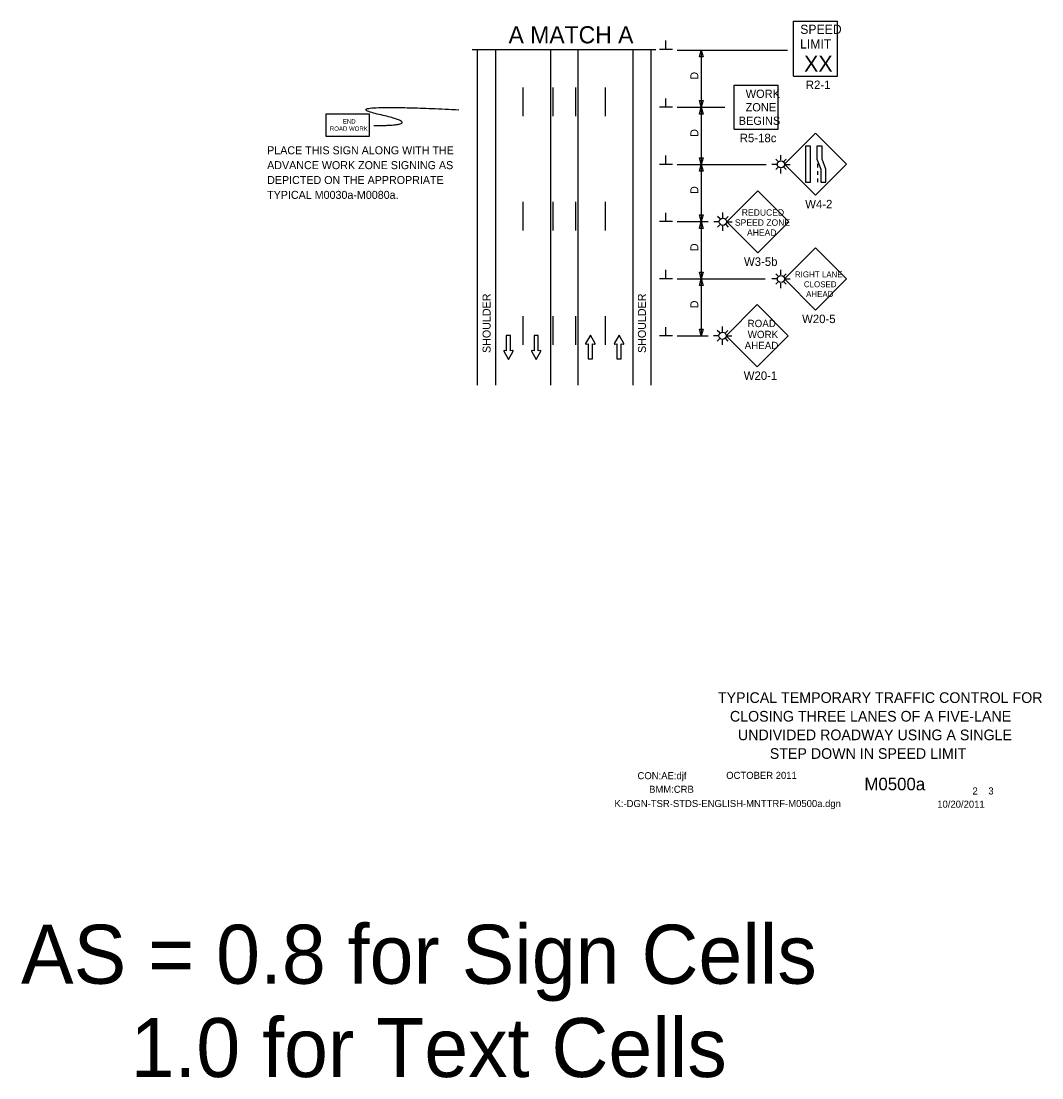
# Model space of a CAD drawing. Extents: x 16738 to 19504, y 5697 to 6916.
# Drawn here: x 17580 to 18473, y 5697 to 6621 of the extents above; entities that cross this region are included whole.
import ezdxf

# ---------------------------------------------------------------- set-up
doc = ezdxf.new("R2010")
doc.units = 0
for name, color, linetype in [('ALI_LEGAL_EX', 7, 'Continuous'), ('BORDER', 7, 'Continuous'), ('BORDER_SIGNAL_WO', 7, 'Continuous'), ('MT_SCRATCH_LEVEL_E', 7, 'Continuous'), ('PAVT_EDGE_EX', 7, 'Continuous'), ('TRAFFIC_SIGNS_PR', 7, 'Continuous'), ('TYPICAL_TEXT_DIMEN_PR', 7, 'Continuous')]:
    doc.layers.add(name, color=color, linetype=linetype)

msp = doc.modelspace()

# ---------------------------------------------------------------- linework, layer by layer
at = {"layer": 'ALI_LEGAL_EX'}
for points in [[(18019.48, 6563.08), (18019.48, 6538.08)], [(18045.48, 6563.08), (18045.48, 6538.08)], [(18065.48, 6563.08), (18065.48, 6538.08)], [(18091.48, 6563.08), (18091.48, 6538.08)], [(18019.48, 6463.08), (18019.48, 6438.08)], [(18045.48, 6463.08), (18045.48, 6438.08)], [(18065.48, 6463.08), (18065.48, 6438.08)], [(18091.48, 6463.08), (18091.48, 6438.08)], [(18019.48, 6363.08), (18019.48, 6338.08)], [(18045.48, 6363.08), (18045.48, 6338.08)], [(18065.48, 6363.08), (18065.48, 6338.08)], [(18091.48, 6363.08), (18091.48, 6338.08)]]:
    msp.add_lwpolyline(points, dxfattribs=at)
at = {"layer": 'MT_SCRATCH_LEVEL_E'}
for p, q in [((18008.68, 6346.05), (18004.93, 6346.05)), ((18004.93, 6346.05), (18004.93, 6332.79)), ((18008.68, 6346.05), (18004.93, 6346.05)), ((18004.93, 6346.05), (18004.93, 6332.79)), ((18008.68, 6332.79), (18008.68, 6346.05)), ((18008.68, 6332.79), (18008.68, 6346.05)), ((18032.93, 6346.05), (18029.19, 6346.05)), ((18029.19, 6346.05), (18029.19, 6332.79)), ((18032.93, 6346.05), (18029.19, 6346.05)), ((18029.19, 6346.05), (18029.19, 6332.79)), ((18032.93, 6332.79), (18032.93, 6346.05)), ((18032.93, 6332.79), (18032.93, 6346.05)), ((18078.44, 6346.51), (18074.33, 6339.27)), ((18078.44, 6346.51), (18074.33, 6339.27)), ((18082.59, 6339.27), (18078.44, 6346.51)), ((18082.59, 6339.27), (18078.44, 6346.51)), ((18103.53, 6346.51), (18099.42, 6339.27)), ((18103.53, 6346.51), (18099.42, 6339.27)), ((18107.68, 6339.27), (18103.53, 6346.51)), ((18107.68, 6339.27), (18103.53, 6346.51)), ((18002.68, 6332.42), (18006.82, 6325.18)), ((18002.68, 6332.42), (18006.82, 6325.18)), ((18004.93, 6332.79), (18003.16, 6333.11)), ((18004.93, 6332.79), (18003.16, 6333.11)), ((18006.82, 6325.18), (18010.94, 6332.42)), ((18006.82, 6325.18), (18010.94, 6332.42)), ((18010.45, 6333.11), (18008.68, 6332.79)), ((18010.45, 6333.11), (18008.68, 6332.79)), ((18026.93, 6332.42), (18031.08, 6325.18)), ((18026.93, 6332.42), (18031.08, 6325.18)), ((18029.19, 6332.79), (18027.41, 6333.11)), ((18029.19, 6332.79), (18027.41, 6333.11)), ((18031.08, 6325.18), (18035.19, 6332.42)), ((18031.08, 6325.18), (18035.19, 6332.42)), ((18034.71, 6333.11), (18032.93, 6332.79)), ((18034.71, 6333.11), (18032.93, 6332.79)), ((18074.81, 6338.59), (18076.59, 6338.9)), ((18074.81, 6338.59), (18076.59, 6338.9)), ((18076.59, 6338.9), (18076.59, 6325.64)), ((18076.59, 6338.9), (18076.59, 6325.64)), ((18080.33, 6325.64), (18080.33, 6338.9)), ((18080.33, 6338.9), (18082.11, 6338.59)), ((18080.33, 6325.64), (18080.33, 6338.9)), ((18080.33, 6338.9), (18082.11, 6338.59)), ((18099.9, 6338.59), (18101.68, 6338.9)), ((18099.9, 6338.59), (18101.68, 6338.9)), ((18101.68, 6338.9), (18101.68, 6325.64)), ((18101.68, 6338.9), (18101.68, 6325.64)), ((18105.42, 6325.64), (18105.42, 6338.9)), ((18105.42, 6338.9), (18107.2, 6338.59)), ((18105.42, 6325.64), (18105.42, 6338.9)), ((18105.42, 6338.9), (18107.2, 6338.59)), ((18076.59, 6325.64), (18080.33, 6325.64)), ((18076.59, 6325.64), (18080.33, 6325.64)), ((18101.68, 6325.64), (18105.42, 6325.64)), ((18101.68, 6325.64), (18105.42, 6325.64))]:
    msp.add_line(p, q, dxfattribs=at)
for centre, start, end in [((18003.09, 6332.65), 80.03619, 209.77312), ((18003.09, 6332.65), 80.03619, 209.77312), ((18010.53, 6332.65), 330.42484, 99.96381), ((18010.53, 6332.65), 330.42484, 99.96381), ((18027.34, 6332.65), 80.03619, 209.77312), ((18027.34, 6332.65), 80.03619, 209.77312), ((18034.78, 6332.65), 330.42484, 99.96381), ((18034.78, 6332.65), 330.42484, 99.96381), ((18074.74, 6339.05), 150.42484, 279.96381), ((18074.74, 6339.05), 150.42484, 279.96381), ((18082.18, 6339.05), 260.03619, 29.77312), ((18082.18, 6339.05), 260.03619, 29.77312), ((18099.83, 6339.05), 150.42484, 279.96381), ((18099.83, 6339.05), 150.42484, 279.96381), ((18107.27, 6339.05), 260.03619, 29.77312), ((18107.27, 6339.05), 260.03619, 29.77312)]:
    msp.add_arc(centre, 0.463, start, end, dxfattribs=at)
at = {"layer": 'PAVT_EDGE_EX'}
for p, q in [((17979.48, 6596.43), (17979.48, 6302.77)), ((17995.48, 6596.43), (17995.48, 6302.77)), ((18043.48, 6596.43), (18043.48, 6302.77)), ((18067.48, 6596.43), (18067.48, 6302.77)), ((18115.48, 6596.43), (18115.48, 6302.77)), ((18131.48, 6596.43), (18131.48, 6302.77))]:
    msp.add_line(p, q, dxfattribs=at)
at = {"layer": 'TRAFFIC_SIGNS_PR'}
for p, q in [((18256.28, 6621.17), (18294.68, 6621.17)), ((18256.28, 6573.17), (18256.28, 6621.17)), ((18294.68, 6573.17), (18294.68, 6621.17)), ((18256.28, 6573.17), (18294.68, 6573.17)), ((18204.34, 6526.68), (18204.34, 6565.08)), ((18204.34, 6565.08), (18242.74, 6565.08)), ((18242.74, 6526.68), (18242.74, 6565.08)), ((18204.34, 6526.68), (18242.74, 6526.68)), ((18275.44, 6523.12), (18248.29, 6495.97)), ((18302.59, 6495.97), (18275.44, 6523.12)), ((18242.69, 6498.42), (18240.58, 6500.53)), ((18245.2, 6499.47), (18245.2, 6503.97)), ((18247.72, 6498.42), (18249.82, 6500.53)), ((18242.05, 6495.91), (18237.21, 6495.91)), ((18242.69, 6493.4), (18240.58, 6491.29)), ((18245.2, 6487.94), (18245.2, 6492.36)), ((18247.72, 6493.4), (18249.82, 6491.29)), ((18248.29, 6495.97), (18275.44, 6468.81)), ((18248.36, 6495.91), (18253.24, 6495.91)), ((18275.44, 6468.81), (18302.59, 6495.97)), ((18277.08, 6496.46), (18277.08, 6493.26)), ((18277.08, 6490.06), (18277.08, 6486.86)), ((18277.08, 6483.66), (18277.08, 6480.46)), ((18224.86, 6472.83), (18197.71, 6445.68)), ((18252.02, 6445.68), (18224.86, 6472.83)), ((18194.4, 6449.25), (18194.4, 6453.75)), ((18191.24, 6445.7), (18186.41, 6445.7)), ((18191.88, 6448.21), (18189.78, 6450.32)), ((18191.88, 6443.19), (18189.78, 6441.08)), ((18196.91, 6448.21), (18199.02, 6450.32)), ((18196.91, 6443.18), (18199.02, 6441.08)), ((18197.55, 6445.7), (18202.43, 6445.7)), ((18197.71, 6445.68), (18224.86, 6418.53)), ((18224.86, 6418.53), (18252.02, 6445.68)), ((18194.4, 6437.73), (18194.4, 6442.14)), ((18275.51, 6422.77), (18248.36, 6395.62)), ((18302.66, 6395.62), (18275.51, 6422.77)), ((18242.69, 6398.13), (18240.58, 6400.24)), ((18245.2, 6399.17), (18245.2, 6403.68)), ((18247.72, 6398.13), (18249.82, 6400.24)), ((18242.05, 6395.62), (18237.21, 6395.62)), ((18242.69, 6393.11), (18240.58, 6391)), ((18245.2, 6387.65), (18245.2, 6392.06)), ((18247.72, 6393.11), (18249.82, 6391)), ((18248.36, 6395.62), (18253.24, 6395.62)), ((18248.36, 6395.62), (18275.51, 6368.47)), ((18275.51, 6368.47), (18302.66, 6395.62)), ((18224.45, 6373.17), (18197.27, 6345.98)), ((18251.64, 6345.98), (18224.45, 6373.17)), ((18191.6, 6348.5), (18189.49, 6350.6)), ((18194.11, 6349.54), (18194.11, 6354.04)), ((18196.63, 6348.5), (18198.73, 6350.6)), ((18190.96, 6345.98), (18186.12, 6345.98)), ((18191.6, 6343.47), (18189.49, 6341.36)), ((18194.11, 6338.02), (18194.11, 6342.43)), ((18196.63, 6343.47), (18198.73, 6341.36)), ((18197.27, 6345.98), (18202.15, 6345.98)), ((18197.27, 6345.98), (18224.45, 6318.8)), ((18224.45, 6318.8), (18251.64, 6345.98))]:
    msp.add_line(p, q, dxfattribs=at)
for points in [[(17846.94, 6520.48), (17885.34, 6520.48), (17885.34, 6539.68), (17846.94, 6539.68)], [(18266.54, 6511.7), (18266.54, 6480.46), (18271.04, 6480.46), (18271.04, 6511.7)], [(18276.68, 6511.7), (18276.68, 6500.52), (18280.02, 6491.64), (18280.02, 6480.46), (18284.52, 6480.46), (18284.52, 6491.64), (18281.17, 6500.52), (18281.17, 6511.7)]]:
    msp.add_lwpolyline(points, close=True, dxfattribs=at)
for centre in [(18245.2, 6495.91), (18194.4, 6445.7), (18245.2, 6395.62), (18194.11, 6345.98)]:
    msp.add_circle(centre, 3.15, dxfattribs=at)
msp.add_open_spline([(17888.94, 6529.86), (17936.17, 6529.86), (17851.15, 6549.2), (17963.45, 6543.71)], degree=2, dxfattribs=at)
at = {"layer": 'TYPICAL_TEXT_DIMEN_PR'}
for p, q in [((18144.61, 6596.43), (18144.61, 6604.22)), ((17975.18, 6596.43), (18135.78, 6596.43)), ((18150.23, 6596.43), (18138.98, 6596.43)), ((18154.48, 6595.78), (18250.87, 6595.78)), ((18173.91, 6589.92), (18175.48, 6595.78)), ((18175.48, 6595.78), (18175.48, 6545.78)), ((18175.48, 6595.78), (18177.05, 6589.92)), ((18175.48, 6589.92), (18173.91, 6589.92)), ((18177.05, 6589.92), (18175.48, 6589.92)), ((18144.61, 6545.78), (18144.61, 6553.57)), ((18150.23, 6545.78), (18138.98, 6545.78)), ((18154.48, 6545.78), (18196.21, 6545.78)), ((18175.48, 6545.78), (18173.91, 6551.65)), ((18173.91, 6551.65), (18175.48, 6551.65)), ((18173.91, 6539.92), (18175.48, 6545.78)), ((18175.48, 6551.65), (18177.05, 6551.65)), ((18177.05, 6551.65), (18175.48, 6545.78)), ((18175.48, 6545.78), (18175.48, 6495.78)), ((18175.48, 6545.78), (18177.05, 6539.92)), ((18175.48, 6539.92), (18173.91, 6539.92)), ((18177.05, 6539.92), (18175.48, 6539.92)), ((18144.61, 6495.78), (18144.61, 6503.57)), ((18175.48, 6495.78), (18173.91, 6501.65)), ((18173.91, 6501.65), (18175.48, 6501.65)), ((18175.48, 6495.78), (18173.91, 6501.65)), ((18173.91, 6501.65), (18175.48, 6501.65)), ((18175.48, 6501.65), (18177.05, 6501.65)), ((18177.05, 6501.65), (18175.48, 6495.78)), ((18175.48, 6501.65), (18177.05, 6501.65)), ((18177.05, 6501.65), (18175.48, 6495.78)), ((18150.23, 6495.78), (18138.98, 6495.78)), ((18154.48, 6495.78), (18232.14, 6495.78)), ((18173.91, 6489.92), (18175.48, 6495.78)), ((18175.48, 6489.92), (18173.91, 6489.92)), ((18175.48, 6495.78), (18175.48, 6445.78)), ((18175.48, 6495.78), (18177.05, 6489.92)), ((18177.05, 6489.92), (18175.48, 6489.92)), ((18144.61, 6445.78), (18144.61, 6453.57)), ((18150.23, 6445.78), (18138.98, 6445.78)), ((18154.48, 6445.78), (18181.52, 6445.78)), ((18175.48, 6445.78), (18173.91, 6451.65)), ((18173.91, 6451.65), (18175.48, 6451.65)), ((18173.91, 6439.92), (18175.48, 6445.78)), ((18175.48, 6451.65), (18177.05, 6451.65)), ((18177.05, 6451.65), (18175.48, 6445.78)), ((18175.48, 6445.78), (18175.48, 6395.78)), ((18175.48, 6445.78), (18177.05, 6439.92)), ((18175.48, 6439.92), (18173.91, 6439.92)), ((18177.05, 6439.92), (18175.48, 6439.92)), ((18144.61, 6395.78), (18144.61, 6403.57)), ((18175.48, 6395.78), (18173.91, 6401.65)), ((18173.91, 6401.65), (18175.48, 6401.65)), ((18175.48, 6401.65), (18177.05, 6401.65)), ((18177.05, 6401.65), (18175.48, 6395.78)), ((18150.23, 6395.78), (18138.98, 6395.78)), ((18154.48, 6395.78), (18231.28, 6395.78)), ((18173.91, 6389.92), (18175.48, 6395.78)), ((18175.48, 6389.92), (18173.91, 6389.92)), ((18175.48, 6395.78), (18175.48, 6345.78)), ((18175.48, 6395.78), (18177.05, 6389.92)), ((18177.05, 6389.92), (18175.48, 6389.92)), ((18144.61, 6345.78), (18144.61, 6353.57)), ((18175.48, 6345.78), (18173.91, 6351.65)), ((18173.91, 6351.65), (18175.48, 6351.65)), ((18175.48, 6351.65), (18177.05, 6351.65)), ((18177.05, 6351.65), (18175.48, 6345.78)), ((18150.23, 6345.78), (18138.98, 6345.78)), ((18154.48, 6345.78), (18181.52, 6345.78))]:
    msp.add_line(p, q, dxfattribs=at)

# ---------------------------------------------------------------- texts
at = {"layer": 'BORDER'}
for s, p in [('TYPICAL TEMPORARY TRAFFIC CONTROL FOR', (18190.04, 6024.8)), ('CLOSING THREE LANES OF A FIVE-LANE', (18200.56, 6008.5)), ('UNDIVIDED ROADWAY USING A SINGLE', (18207.56, 5992.2)), ('STEP DOWN IN SPEED LIMIT', (18235.42, 5975.9))]:
    msp.add_text(s, height=9.3, dxfattribs=at).set_placement(p)
at = {"layer": 'BORDER_SIGNAL_WO'}
for s, height, p in [('CON:AE:djf', 6.2, (18119.69, 5958.06)), ('    OCTOBER 2011    ', 6.2, (18188.08, 5958.34)), ('    M0500a   ', 11, (18301.86, 5948.38)), ('BMM:CRB   ', 6.2, (18129.81, 5946.17)), (' 2    3 ', 6.2, (18410.45, 5944.7)), ('K:-DGN-TSR-STDS-ENGLISH-MNTTRF-M0500a.dgn        ', 6.2, (18099.55, 5933.71)), ('10/20/2011    ', 6.2, (18381.93, 5933.13)), ('AS = 0.8 for Sign Cells', 51.6096, (17580.32, 5779.18)), ('     1.0 for Text Cells', 51.6096, (17580.32, 5697.57))]:
    msp.add_text(s, height=height, dxfattribs=at).set_placement(p)
at = {"layer": 'TRAFFIC_SIGNS_PR'}
for s, height, p in [('SPEED', 8, (18262.04, 6610.03)), ('LIMIT', 8, (18261.88, 6597.23)), ('XX', 14.031, (18265.39, 6576.93)), ('R2-1', 7.44, (18266.95, 6561.73)), ('WORK', 7.217, (18214.34, 6554.04)), ('ZONE', 7.217, (18214.22, 6542.23)), ('END', 3.831, (17861.95, 6531.61)), ('BEGINS', 7.217, (18208.15, 6530.42)), ('ROAD WORK', 3.831, (17850.55, 6525.22)), ('R5-18c', 7.44, (18209.15, 6515.24)), ('PLACE THIS SIGN ALONG WITH THE', 7, (17795.67, 6504.7)), ('ADVANCE WORK ZONE SIGNING AS', 7, (17795.67, 6491.7)), ('DEPICTED ON THE APPROPRIATE', 7, (17795.67, 6478.7)), ('TYPICAL M0030a-M0080a.', 7, (17795.67, 6465.7)), ('W4-2', 7.44, (18266.4, 6457.38)), ('REDUCED', 5.6, (18210.92, 6450.99)), ('SPEED ZONE', 5.6, (18204.91, 6442.19)), ('AHEAD', 5.6, (18215.47, 6433.39)), ('W3-5b', 7.44, (18212.82, 6407.09)), ('RIGHT LANE', 5.2, (18257.43, 6397.01)), ('CLOSED', 5.2, (18265.22, 6388.41)), ('AHEAD', 5.2, (18267.17, 6379.81)), ('ROAD', 6.408, (18215.98, 6353.53)), ('W20-5', 7.44, (18263.68, 6357.03)), ('WORK', 6.408, (18216.09, 6343.92)), ('AHEAD', 6.408, (18213.4, 6334.3)), ('W20-1', 7.449, (18212.61, 6307.34))]:
    msp.add_text(s, height=height, dxfattribs=at).set_placement(p)
at = {"layer": 'TYPICAL_TEXT_DIMEN_PR'}
msp.add_text('A MATCH A', height=15, dxfattribs=at).set_placement((18006.9, 6601.72))
for s, p in [('D', (18172.92, 6570)), ('D', (18172.92, 6520)), ('D', (18172.92, 6470)), ('D', (18172.92, 6420)), ('SHOULDER', (17991.17, 6330.9)), ('SHOULDER', (18127.07, 6330.9)), ('D', (18172.92, 6370))]:
    msp.add_text(s, height=7, rotation=90, dxfattribs=at).set_placement(p)

doc.saveas('drawing.dxf')
